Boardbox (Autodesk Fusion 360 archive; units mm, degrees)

design "Boardbox" references "BUTTONBOARDCARROT"
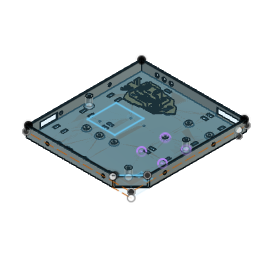
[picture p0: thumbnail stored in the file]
sketch "Sketch1" plane through (0, 0, 0) normal (0, 0, 1) x axis (1, 0, 0)
box_primitive "BoxPrimitive1" DistanceX 220 DistanceY 200 DistanceZ 20 OffsetDistanceX 0 OffsetDistanceY 0
shell "Shell1" innerThickness 2
sketch "Sketch3" plane through (200, 0, 0) normal (1, 0, 0) x axis (0, 1, 0)
  line L1 (-220, 0) -> (-220, 20)
  line L2 (0, 0) -> (-220, 0)
  line L3 (0, 20) -> (0, 0)
  line L4 (-220, 20) -> (0, 20)
  line L5 (-15, 10) -> (-15, 0)
  line L6 (-220, 10) -> (0, 10)
  point P6 (-15, 0)
  point P8 (0, 10)
  point P9 (-220, 10)
  point P7 (-15, 10)
  coincident L2 P6
  perpendicular L2 L5
  coincident L3 P8
  coincident L1 P9
  perpendicular L1 L6
  dimension "d7" distance P6 P7 = 10
hole "Hole1" HoleDepth 210 HoleDiameter 6 TipAngle 180
hole "Hole2" HoleDepth 210 HoleDiameter 6 TipAngle 180
sketch "Sketch4" plane through (0, -220, 0) normal (0, -1, 0) x axis (1, 0, 0)
  line L1 (0, 0) -> (0, 20)
  line L2 (200, 0) -> (0, 0)
  line L3 (200, 20) -> (200, 0)
  line L4 (0, 20) -> (200, 20)
  line L5 (0, 9.9996) -> (200, 9.9996)
  point P6 (200, 9.9996)
  point P7 (0, 9.9996)
  coincident L3 P6
  coincident L1 P7
  perpendicular L1 L5
hole "Hole3" HoleDepth 180 HoleDiameter 6 TipAngle 180
hole "Hole4" HoleDepth 145 HoleDiameter 6 TipAngle 180
sketch "Sketch5" plane through (0, -220, 0) normal (0, -1, 0) x axis (1, 0, 0)
  line L1 (165, 0) -> (200, 0)
  line L2 (165, 18) -> (165, 0)
  point P2 (200, 0)
  point P3 (165, 0)
  horizontal L1
  perpendicular L1 L2
  dimension "d20" distance P2 P3 = 35
sketch "Sketch6" plane through (0, -220, 0) normal (0, -1, 0) x axis (1, 0, 0)
sketch "Sketch7" plane through (0, 0, 20) normal (0, 0, 1) x axis (-1, 0, 0)
  line L1 (-2, 2) -> (-2, 218)
  line L2 (-198, 2) -> (-2, 2)
  line L3 (-198, 218) -> (-198, 2)
  line L4 (-2, 218) -> (-198, 218)
  line L5 (-200, 220) -> (0, 220)
  line L6 (-200, 0) -> (-200, 220)
  line L7 (0, 0) -> (-200, 0)
  line L8 (0, 220) -> (0, 0)
  line L9 (-200, 185) -> (-200, 220)
  line L10 (-200, 185) -> (-165, 220)
  line L11 (-200, 220) -> (-200, 185)
  line L12 (-200, 220) -> (-165, 220)
  line L13 (-200, 220) -> (-200, 185)
  line L14 (-165, 220) -> (-200, 220)
  point P7 (-200, 220)
  point P10 (-200, 220)
  point P11 (-200, 185)
  point P12 (-165, 220)
  point P13 (-200, 220)
  point P14 (-200, 220)
  point P15 (-200, 220)
  point P16 (-200, 220)
  coincident P7 P10
  coincident L6 P11
  coincident L5 P12
  coincident P7 P13
  coincident P7 P14
  coincident P7 P15
  coincident P7 P16
  dimension "d21" distance P10 P11 = 35
extrude "Extrude1" cut sketch "Sketch7" profile of L3 L4 L5 L6 L9 L10 L11 L12 L13 L14 against normal blind 27
sketch "Sketch8" plane through (0, 0, 0) normal (0, 0, 1) x axis (1, 0, 0)
  line L1 (165, -220) -> (200, -185)
  line L2 (162.4442, -220) -> (165, -220)
  line L3 (200, -182.9254) -> (162.4442, -220)
  line L4 (200, -185) -> (200, -182.9254)
  line L5 (200, -185) -> (165, -220)
  line L6 (200, -182.9254) -> (200, -185)
  horizontal L2
  perpendicular L2 L4
extrude "Extrude2" add sketch "Sketch8" along normal blind 18
sketch "Sketch9" plane through (0, 0, 0) normal (-1, 0, 0) x axis (0, -1, 0)
  line L1 (0, 0) -> (0, 20)
  line L2 (220, 0) -> (0, 0)
  line L3 (220, 20) -> (220, 0)
  line L4 (0, 20) -> (220, 20)
  line L5 (195.4309, 13.9647) -> (162.5688, 13.9647)
  line L6 (195.4309, 2.2555) -> (195.4309, 13.9647)
  line L7 (162.5688, 2.2555) -> (195.4309, 2.2555)
  line L8 (162.5688, 13.9647) -> (162.5688, 2.2555)
  circle C1 centre (155.6636, 9.6305) radius 3
  circle C2 centre (62.6686, 9.9839) radius 3
  horizontal L5
  vertical L6
  horizontal L7
  vertical L8
extrude "Extrude3" cut sketch "Sketch9" profile of L5 L6 L7 L8 against normal blind 5
hole "Hole5" HoleDepth 5 HoleDiameter 7.5 TipAngle 180
rectangular_pattern "R-Pattern1" uSpaceDistance 27 vSpaceDistance 0
sketch "Sketch10" plane through (0, 0, 0) normal (0, 1, 0) x axis (-1, 0, 0)
  line L1 (-200, 0) -> (-200, 20)
  line L2 (0, 0) -> (-200, 0)
  line L3 (0, 20) -> (0, 0)
  line L4 (-200, 20) -> (0, 20)
  line L5 (-191, 1.956) -> (-145.4938, 1.956)
  line L6 (-191, 13.3548) -> (-191, 1.956)
  line L7 (-145.4938, 13.3548) -> (-191, 13.3548)
  line L8 (-145.4938, 1.956) -> (-145.4938, 13.3548)
  circle C1 centre (-58.442, 9.125) radius 3.75
  circle C2 centre (-44.942, 9.125) radius 3.75
  circle C3 centre (-31.442, 9.125) radius 3.75
  horizontal L5
  vertical L6
  horizontal L7
  vertical L8
extrude "Extrude4" cut sketch "Sketch10" profile of L5 L6 L7 L8 against normal blind 5
cylinder_primitive "CylinderPrimitive1" Height 3 Diameter 10
fillet "Fillet1" radius 2
hole "Hole6" HoleDepth 4 HoleDiameter 2.93 TipAngle 180
rectangular_pattern "R-Pattern2" uSpaceDistance 25 vSpaceDistance 0
rectangular_pattern "R-Pattern3" uSpaceDistance 60 vSpaceDistance 0
rectangular_pattern "R-Pattern4" uSpaceDistance -25 vSpaceDistance 0
rectangular_pattern "R-Pattern5" uSpaceDistance -45 vSpaceDistance 0
rectangular_pattern "R-Pattern6" uSpaceDistance -65 vSpaceDistance 0
rectangular_pattern "R-Pattern7" uSpaceDistance 80 vSpaceDistance 0
rectangular_pattern "R-Pattern8" uSpaceDistance 90 vSpaceDistance 0
rectangular_pattern "R-Pattern9" uSpaceDistance -35 vSpaceDistance 160
rectangular_pattern "R-Pattern10" uSpaceDistance -115 vSpaceDistance 5
sketch "Sketch17" plane through (0, 0, 5) normal (0, 0, 1) x axis (-1, 0, 0)
  circle C1 centre (-30, 125) radius 1.465
  circle C2 centre (-30, 125) radius 5
  circle C3 centre (-30, 125) radius 8.4853
  concentric C1 C3
extrude "Extrude5" cut sketch "Sketch17" against normal blind 3
sketch "Sketch18" plane through (0, 0, 5) normal (0, 0, 1) x axis (-1, 0, 0)
  line L1 (-163.1266, 149.3318) -> (-184.7539, 149.3318)
  line L2 (-163.1266, 76.8403) -> (-163.1266, 149.3318)
  line L3 (-184.7539, 76.8403) -> (-163.1266, 76.8403)
  line L4 (-184.7539, 149.3318) -> (-184.7539, 76.8403)
  circle C1 centre (-95, 45) radius 1.465
  circle C2 centre (-95, 45) radius 5
  horizontal L1
  vertical L2
  horizontal L3
  vertical L4
extrude "Extrude6" cut sketch "Sketch18" against normal blind 3
rectangular_pattern "R-Pattern11" uSpaceDistance 15 vSpaceDistance 0
sketch "Sketch19" plane through (0, 0, 5) normal (0, 0, 1) x axis (-1, 0, 0)
  line L1 (-20, 213.7402) -> (-37.129, 213.7402)
  line L2 (-20, 195) -> (-20, 213.7402)
  line L3 (-37.129, 195) -> (-20, 195)
  line L4 (-37.129, 213.7402) -> (-37.129, 195)
  circle C1 centre (-30, 205) radius 1.465
  circle C2 centre (-30, 205) radius 5
  horizontal L1
  vertical L2
  horizontal L3
  vertical L4
extrude "Extrude7" cut sketch "Sketch19" against normal blind 3
sketch "Sketch20" plane through (0, 0, 5) normal (0, 0, 1) x axis (1, 0, 0)
  circle C1 centre (94.9495, -90.5388) radius 11.6431
  circle C2 centre (134.4633, -135.3211) radius 12.0807
extrude "Extrude8" cut sketch "Sketch20" against normal blind 3
sketch "Sketch21" plane through (0, 0, 5) normal (0, 0, 1) x axis (-1, 0, 0)
  line L1 (-33.3118, 81.7439) -> (-85.2877, 81.7439)
  line L2 (-33.3118, 136.5548) -> (-33.3118, 81.7439)
  line L3 (-85.2877, 136.5548) -> (-33.3118, 136.5548)
  line L4 (-85.2877, 81.7439) -> (-85.2877, 136.5548)
  circle C1 centre (-70, 90) radius 1.465
  circle C2 centre (-70, 90) radius 5
  horizontal L1
  vertical L2
  horizontal L3
  vertical L4
extrude "Extrude9" cut sketch "Sketch21" against normal blind 3
sketch "Sketch22" plane through (0, 0, 2) normal (0, 0, 1) x axis (-1, 0, 0)
  line L1 (-191, 5) -> (-191, 2)
  line L2 (-145.4938, 5) -> (-191, 5)
  line L3 (-145.4938, 2) -> (-145.4938, 5)
  line L4 (-2, 2) -> (-145.4938, 2)
  line L5 (-2, 218) -> (-2, 2)
  line L6 (-164.4702, 218) -> (-2, 218)
  line L7 (-198, 184.8998) -> (-164.4702, 218)
  line L8 (-198, 2) -> (-198, 184.8998)
  line L9 (-191, 2) -> (-198, 2)
  line L10 (-185, 180) -> (-190, 180)
  line L11 (-185, 170) -> (-185, 180)
  line L12 (-190, 170) -> (-185, 170)
  line L13 (-190, 180) -> (-190, 170)
  line L14 (-170, 180) -> (-175, 180)
  line L15 (-170, 170) -> (-170, 180)
  line L16 (-175, 170) -> (-170, 170)
  line L17 (-175, 180) -> (-175, 170)
  circle C1 centre (-45, 125) radius 1.465
  circle C2 centre (-70, 90) radius 1.465
  circle C3 centre (-95, 90) radius 1.465
  circle C4 centre (-30, 205) radius 1.465
  circle C5 centre (-30, 125) radius 1.465
  circle C6 centre (-95, 147.5) radius 7
  circle C7 centre (-135, 45) radius 7
  circle C8 centre (-95, 45) radius 7
  circle C9 centre (-70, 150) radius 7
  circle C10 centre (-45, 150) radius 7
  circle C11 centre (-30, 45) radius 7
  circle C12 centre (-175, 45) radius 7
  circle C13 centre (-95, 205) radius 7
  circle C14 centre (-45, 205) radius 7
  circle C15 centre (-135, 135) radius 1.465
  circle C16 centre (-175, 135) radius 1.465
  circle C17 centre (-175, 90) radius 1.465
  circle C18 centre (-135, 90) radius 7
  horizontal L10
  vertical L11
  horizontal L12
  vertical L13
  horizontal L14
  vertical L15
  horizontal L16
  vertical L17
sketch "Sketch26" plane through (0, 0, 2) normal (0, 0, 1) x axis (-1, 0, 0)
  line L1 (-191, 5) -> (-191, 2)
  line L2 (-145.4938, 5) -> (-191, 5)
  line L3 (-145.4938, 2) -> (-145.4938, 5)
  line L4 (-2, 2) -> (-145.4938, 2)
  line L5 (-2, 218) -> (-2, 2)
  line L6 (-164.4702, 218) -> (-2, 218)
  line L7 (-198, 184.8998) -> (-164.4702, 218)
  line L8 (-198, 2) -> (-198, 184.8998)
  line L9 (-191, 2) -> (-198, 2)
  circle C1 centre (-45, 125) radius 1.465
  circle C2 centre (-70, 90) radius 1.465
  circle C3 centre (-135, 135) radius 1.465
  circle C4 centre (-95, 90) radius 1.465
  circle C5 centre (-30, 205) radius 1.465
  circle C6 centre (-175, 135) radius 1.465
  circle C7 centre (-175, 90) radius 1.465
  circle C8 centre (-30, 125) radius 1.465
  circle C9 centre (-95, 147.5) radius 7
  circle C10 centre (-135, 90) radius 7
  circle C11 centre (-135, 45) radius 7
  circle C12 centre (-95, 45) radius 7
  circle C13 centre (-70, 150) radius 7
  circle C14 centre (-45, 150) radius 7
  circle C15 centre (-30, 45) radius 7
  circle C16 centre (-175, 45) radius 7
  circle C17 centre (-95, 205) radius 7
  circle C18 centre (-45, 205) radius 7
  circle C19 centre (-165, 190) radius 5.35
  circle C20 centre (-10, 110) radius 5.099
  circle C21 centre (-175, 90) radius 5
  concentric C7 C21
extrude "Extrude12" add sketch "Sketch26" profile of C19 along normal blind 16
fillet "Fillet2" radius 2
hole "Hole7" HoleDepth 10 HoleDiameter 3.5 TipAngle 118
thread "Thread2"
sketch "Sketch27" plane through (0, 0, 2) normal (0, 0, 1) x axis (-1, 0, 0)
  line L1 (-191, 5) -> (-191, 2)
  line L2 (-145.4938, 5) -> (-191, 5)
  line L3 (-145.4938, 2) -> (-145.4938, 5)
  line L4 (-2, 2) -> (-145.4938, 2)
  line L5 (-2, 218) -> (-2, 2)
  line L6 (-164.4702, 218) -> (-2, 218)
  line L7 (-198, 184.8998) -> (-164.4702, 218)
  line L8 (-198, 2) -> (-198, 184.8998)
  line L9 (-191, 2) -> (-198, 2)
  circle C1 centre (-45, 205) radius 7
  circle C2 centre (-95, 205) radius 7
  circle C3 centre (-175, 45) radius 7
  circle C4 centre (-30, 45) radius 7
  circle C5 centre (-45, 150) radius 7
  circle C6 centre (-70, 150) radius 7
  circle C7 centre (-95, 45) radius 7
  circle C8 centre (-135, 45) radius 7
  circle C9 centre (-135, 90) radius 7
  circle C10 centre (-95, 147.5) radius 7
  circle C11 centre (-30, 125) radius 1.465
  circle C12 centre (-175, 90) radius 1.465
  circle C13 centre (-175, 135) radius 1.465
  circle C14 centre (-30, 205) radius 1.465
  circle C15 centre (-95, 90) radius 1.465
  circle C16 centre (-135, 135) radius 1.465
  circle C17 centre (-70, 90) radius 1.465
  circle C18 centre (-45, 125) radius 1.465
  circle C19 centre (-165, 190) radius 7.35
extrude "Extrude13" add sketch "Sketch26" profile of C20 along normal blind 17
extrude "Extrude14" add sketch "Sketch26" profile of C7 C21 along normal blind 17
hole "Hole8" HoleDepth 10 HoleDiameter 3.5 TipAngle 118
thread "Thread3"
fillet "Fillet3" radius 2
thread "Thread4"
fillet "Fillet4" radius 2
sketch "Sketch28" plane through (0, 0, 20) normal (0, 0, 1) x axis (-1, 0, 0)
  line L1 (-167, 218) -> (-165, 220)
  line L2 (-2, 218) -> (-167, 218)
  line L3 (-2, 2) -> (-2, 218)
  line L4 (-198, 2) -> (-2, 2)
  line L5 (-198, 187) -> (-198, 2)
  line L6 (-200, 185) -> (-198, 187)
  line L7 (-200, 0) -> (-200, 185)
  line L8 (0, 0) -> (-200, 0)
  line L9 (0, 220) -> (0, 0)
  line L10 (-165, 220) -> (0, 220)
  line L11 (-2, 218) -> (-2, 2)
  line L12 (-167, 218) -> (-2, 218)
  line L13 (-198, 186.964) -> (-167, 218)
  line L14 (-198, 2) -> (-198, 187)
  line L15 (-2, 2) -> (-198, 2)
  point P5 (-2, 2)
  point P12 (-2, 2)
  point P4 (-2, 218)
  point P13 (-2, 218)
  point P14 (-2, 218)
  point P15 (-198, 186.964)
  point P3 (-167, 218)
  point P16 (-167, 218)
  point P7 (-198, 187)
  point P17 (-198, 187)
  point P6 (-198, 2)
  point P18 (-198, 2)
  point P19 (-198, 2)
  point P20 (-2, 2)
  coincident P5 P12
  coincident P4 P13
  coincident P4 P14
  coincident L5 P15
  coincident P3 P16
  coincident P7 P17
  coincident P6 P18
  coincident P6 P19
  coincident P5 P20
extrude "Extrude15" new body sketch "Sketch28" profile of L2 L3 L4 L5 L11 L12 L13 L14 L15 along normal blind 2
sketch "Sketch29" plane through (0, 0, 2) normal (0, 0, 1) x axis (-1, 0, 0)
hole "Hole9" HoleDepth 2 HoleDiameter 3.5 TipAngle 118 CSDiameter 3.85 CSAngle 90
hole "Hole10" HoleDepth 2 HoleDiameter 3.5 TipAngle 118 CSDiameter 3.85 CSAngle 90
hole "Hole11" HoleDepth 2 HoleDiameter 3.5 TipAngle 118 CSDiameter 3.85 CSAngle 90
hole "Hole12" HoleDepth 2 HoleDiameter 3.5 TipAngle 118 CSDiameter 3.85 CSAngle 90
sketch "Sketch30" plane through (0, 0, 22) normal (0, 0, 1) x axis (-1, 0, 0)
  line L1 (-2, 2) -> (-198, 2)
  line L2 (-2, 218) -> (-2, 2)
  line L3 (-167, 218) -> (-2, 218)
  line L4 (-198, 186.964) -> (-167, 218)
  line L5 (-198, 2) -> (-198, 186.964)
  circle C1 centre (-165.0337, 189.9926) radius 1.925
  circle C2 centre (-175.0244, 89.9638) radius 1.925
  circle C3 centre (-10.0009, 109.9884) radius 1.925
component_insert "Component Insert"
position "Position1"
hole "Hole13" HoleDepth 3.5 HoleDiameter 3.5 TipAngle 118
extrude "Extrude10" cut sketch "Sketch22" profile of L10 L11 L12 L13 L14 L15 L16 L17 against normal blind 3
rectangular_pattern "R-Pattern12" uSpaceDistance -155 vSpaceDistance 0
work_plane "WorkPlane1"
mirror "Mirror1" mirrorStitchTolerance 0.1
sketch "Sketch24" plane through (0, 0, 2) normal (0, 0, 1) x axis (-1, 0, 0)
  line L1 (-30, 25) -> (-30, 15)
  line L2 (-25, 25) -> (-30, 25)
  line L3 (-25, 15) -> (-25, 25)
  line L4 (-30, 15) -> (-25, 15)
  line L5 (-15, 25) -> (-15, 15)
  line L6 (-10, 25) -> (-15, 25)
  line L7 (-10, 15) -> (-10, 25)
  line L8 (-15, 15) -> (-10, 15)
  line L9 (-30, 76.6667) -> (-30, 66.6667)
  line L10 (-25, 76.6667) -> (-30, 76.6667)
  line L11 (-25, 66.6667) -> (-25, 76.6667)
  line L12 (-30, 66.6667) -> (-25, 66.6667)
  line L13 (-15, 76.6667) -> (-15, 66.6667)
  line L14 (-10, 76.6667) -> (-15, 76.6667)
  line L15 (-10, 66.6667) -> (-10, 76.6667)
  line L16 (-15, 66.6667) -> (-10, 66.6667)
  line L17 (-30, 123.535) -> (-30, 118.3333)
  line L18 (-30, 128.3333) -> (-30, 126.465)
  line L19 (-25, 128.3333) -> (-30, 128.3333)
  line L20 (-25, 118.3333) -> (-25, 128.3333)
  line L21 (-30, 118.3333) -> (-25, 118.3333)
  line L22 (-15, 128.3333) -> (-15, 118.3333)
  line L23 (-10, 128.3333) -> (-15, 128.3333)
  line L24 (-10, 118.3333) -> (-10, 128.3333)
  line L25 (-15, 118.3333) -> (-10, 118.3333)
  line L26 (-30, 180) -> (-30, 170)
  line L27 (-25, 180) -> (-30, 180)
  line L28 (-25, 170) -> (-25, 180)
  line L29 (-30, 170) -> (-25, 170)
  line L30 (-15, 180) -> (-15, 170)
  line L31 (-10, 180) -> (-15, 180)
  line L32 (-10, 170) -> (-10, 180)
  line L33 (-15, 170) -> (-10, 170)
  line L34 (-170, 15) -> (-170, 25)
  line L35 (-175, 15) -> (-170, 15)
  line L36 (-175, 25) -> (-175, 15)
  line L37 (-170, 25) -> (-175, 25)
  line L38 (-185, 15) -> (-185, 25)
  line L39 (-190, 15) -> (-185, 15)
  line L40 (-190, 25) -> (-190, 15)
  line L41 (-185, 25) -> (-190, 25)
  line L42 (-170, 66.6667) -> (-170, 76.6667)
  line L43 (-175, 66.6667) -> (-170, 66.6667)
  line L44 (-175, 76.6667) -> (-175, 66.6667)
  line L45 (-170, 76.6667) -> (-175, 76.6667)
  line L46 (-185, 66.6667) -> (-185, 76.6667)
  line L47 (-190, 66.6667) -> (-185, 66.6667)
  line L48 (-190, 76.6667) -> (-190, 66.6667)
  line L49 (-185, 76.6667) -> (-190, 76.6667)
  line L50 (-170, 118.3333) -> (-170, 128.3333)
  line L51 (-175, 118.3333) -> (-170, 118.3333)
  line L52 (-175, 128.3333) -> (-175, 118.3333)
  line L53 (-170, 128.3333) -> (-175, 128.3333)
  line L54 (-185, 118.3333) -> (-185, 128.3333)
  line L55 (-190, 118.3333) -> (-185, 118.3333)
  line L56 (-190, 128.3333) -> (-190, 118.3333)
  line L57 (-185, 128.3333) -> (-190, 128.3333)
  line L58 (-170, 170) -> (-170, 180)
  line L59 (-175, 170) -> (-170, 170)
  line L60 (-175, 180) -> (-175, 170)
  line L61 (-170, 180) -> (-175, 180)
  line L62 (-185, 170) -> (-185, 180)
  line L63 (-190, 170) -> (-185, 170)
  line L64 (-190, 180) -> (-190, 170)
  line L65 (-185, 180) -> (-190, 180)
  line L66 (-191, 5) -> (-191, 2)
  line L67 (-145.4938, 5) -> (-191, 5)
  line L68 (-145.4938, 2) -> (-145.4938, 5)
  line L69 (-2, 2) -> (-145.4938, 2)
  line L70 (-2, 218) -> (-2, 2)
  line L71 (-164.4702, 218) -> (-2, 218)
  line L72 (-198, 184.8998) -> (-164.4702, 218)
  line L73 (-198, 2) -> (-198, 184.8998)
  line L74 (-191, 2) -> (-198, 2)
  line L75 (-65.4464, 12.6094) -> (-55.4464, 12.6094)
  line L76 (-65.4464, 7.6094) -> (-65.4464, 12.6094)
  line L77 (-55.4464, 7.6094) -> (-65.4464, 7.6094)
  line L78 (-55.4464, 12.6094) -> (-55.4464, 7.6094)
  arc A1 centre (-30, 125) radius 1.465 clockwise from (-30, 123.535) to (-30, 126.465)
  circle C1 centre (-45, 125) radius 1.465
  circle C2 centre (-70, 90) radius 1.465
  circle C3 centre (-135, 135) radius 1.465
  circle C4 centre (-95, 90) radius 1.465
  circle C5 centre (-30, 205) radius 1.465
  circle C6 centre (-175, 135) radius 1.465
  circle C7 centre (-95, 147.5) radius 7
  circle C8 centre (-135, 90) radius 7
  circle C9 centre (-135, 45) radius 7
  circle C10 centre (-95, 45) radius 7
  circle C11 centre (-70, 150) radius 7
  circle C12 centre (-45, 150) radius 7
  circle C13 centre (-30, 45) radius 7
  circle C14 centre (-175, 45) radius 7
  circle C15 centre (-95, 205) radius 7
  circle C16 centre (-45, 205) radius 7
  circle C17 centre (-10, 110) radius 7.099
  circle C18 centre (-165, 190) radius 7.35
  circle C19 centre (-175, 90) radius 7
  point P94 (-55.4464, 12.6094)
  point P95 (-65.4464, 12.6094)
  point P97 (-55.4464, 7.6094)
  horizontal L75
  vertical L76
  horizontal L77
  vertical L78
  dimension "d102" distance P94 P95 = 10
  dimension "d103" distance P94 P97 = 5
extrude "Extrude11" cut sketch "Sketch24" profile of L75 L76 L77 L78 against normal blind 3
rectangular_pattern "R-Pattern13" uSpaceDistance -80 vSpaceDistance -10
work_plane "WorkPlane2"
mirror "Mirror2" mirrorStitchTolerance 0.1
work_plane "WorkPlane3" sketch "Sketch4"
mirror "Mirror3" mirrorStitchTolerance 0.1
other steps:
thread "Thread1"

design "BUTTONBOARDCARROT"
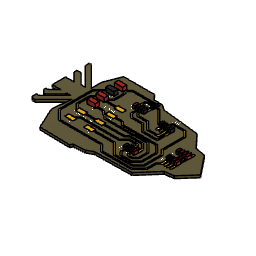
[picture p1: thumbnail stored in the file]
sketch "Outline" plane through (0, 0, 0) normal (0, 0, 1) x axis (1, 0, 0)
  line L1 (21.1401, 38.8908) -> (20.32, 39.7109)
  line L2 (22.86, 38.8908) -> (21.1401, 38.8908)
  line L3 (34.29, 50.3208) -> (22.86, 38.8908)
  line L4 (33.02, 38.8908) -> (34.29, 50.3208)
  line L5 (39.1448, 25.654) -> (33.02, 38.8908)
  line L6 (57.7953, 25.273) -> (39.1448, 25.654)
  line L7 (58.5717, 26.8114) -> (57.7953, 25.273)
  line L8 (65.6734, 27.3194) -> (58.5717, 26.8114)
  line L9 (69.342, 29.337) -> (65.6734, 27.3194)
  line L10 (91.948, 29.718) -> (69.342, 29.337)
  line L11 (101.219, 40.259) -> (91.948, 29.718)
  line L12 (106.68, 41.021) -> (101.219, 40.259)
  line L13 (114.3, 49.53) -> (106.68, 41.021)
  line L14 (105.029, 61.214) -> (114.3, 49.53)
  line L15 (98.679, 62.484) -> (105.029, 61.214)
  line L16 (91.186, 70.485) -> (98.679, 62.484)
  line L17 (68.326, 73.025) -> (91.186, 70.485)
  line L18 (64.897, 75.311) -> (68.326, 73.025)
  line L19 (59.817, 75.311) -> (64.897, 75.311)
  line L20 (57.15, 78.359) -> (59.817, 75.311)
  line L21 (38.1, 78.359) -> (57.15, 78.359)
  line L22 (34.29, 68.58) -> (38.1, 78.359)
  line L23 (34.29, 62.23) -> (34.29, 68.58)
  line L24 (21.59, 74.93) -> (34.29, 62.23)
  line L25 (20.32, 74.93) -> (21.59, 74.93)
  line L26 (20.32, 72.39) -> (20.32, 74.93)
  line L27 (31.75, 60.96) -> (20.32, 72.39)
  line L28 (29.2707, 60.96) -> (31.75, 60.96)
  line L29 (22.9207, 67.31) -> (29.2707, 60.96)
  line L30 (20.32, 67.31) -> (22.9207, 67.31)
  line L31 (20.32, 65.4972) -> (20.32, 67.31)
  line L32 (25.542, 60.2752) -> (20.32, 65.4972)
  line L33 (20.32, 60.2752) -> (25.542, 60.2752)
  line L34 (20.32, 52.07) -> (20.32, 60.2752)
  line L35 (25.542, 52.07) -> (20.32, 52.07)
  line L36 (21.732, 48.26) -> (25.542, 52.07)
  line L37 (20.32, 48.26) -> (21.732, 48.26)
  line L38 (20.32, 46.848) -> (20.32, 48.26)
  line L39 (22.2767, 44.8913) -> (20.32, 46.848)
  line L40 (22.931, 44.8913) -> (22.2767, 44.8913)
  line L41 (29.21, 51.1703) -> (22.931, 44.8913)
  line L42 (29.21, 52.07) -> (29.21, 51.1703)
  line L43 (31.75, 52.07) -> (29.21, 52.07)
  line L44 (21.9603, 42.2803) -> (31.75, 52.07)
  line L45 (20.32, 42.2803) -> (21.9603, 42.2803)
  line L46 (20.32, 39.7109) -> (20.32, 42.2803)
canvas "Canvas1" bodies "Board"
canvas "Canvas2" bodies "Board"
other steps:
pcbextrude "PCBExtrude1"
box_primitive "BoxPrimitive1" DistanceX 1.27 DistanceY 2.54 DistanceZ 1.897 OffsetDistanceX 0 OffsetDistanceY 0
box_primitive "BoxPrimitive1" DistanceX 2.54 DistanceY 5.08 DistanceZ 2.4419 OffsetDistanceX 0 OffsetDistanceY 0
extrude "Extrude1" sketch "Outline" blind 1.5 bodies "Board"
pcbextrude "PCBExtrude1"
box_primitive "BoxPrimitive1" DistanceX 4.572 DistanceY 2.159 DistanceZ 0.1 OffsetDistanceX 0 OffsetDistanceY 0
pcbextrude "PCBExtrude1"
pcbextrude "PCBExtrude"
create_component "CreateComponent1"
create_component "CreateComponent2"
create_component "CreateComponent3"
create_component "CreateComponent4"
as_built_joint "As-built1"
create_component "CreateComponent4"
create_component "CreateComponent17"
create_component "CreateComponent18"
named bodies: "Board"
